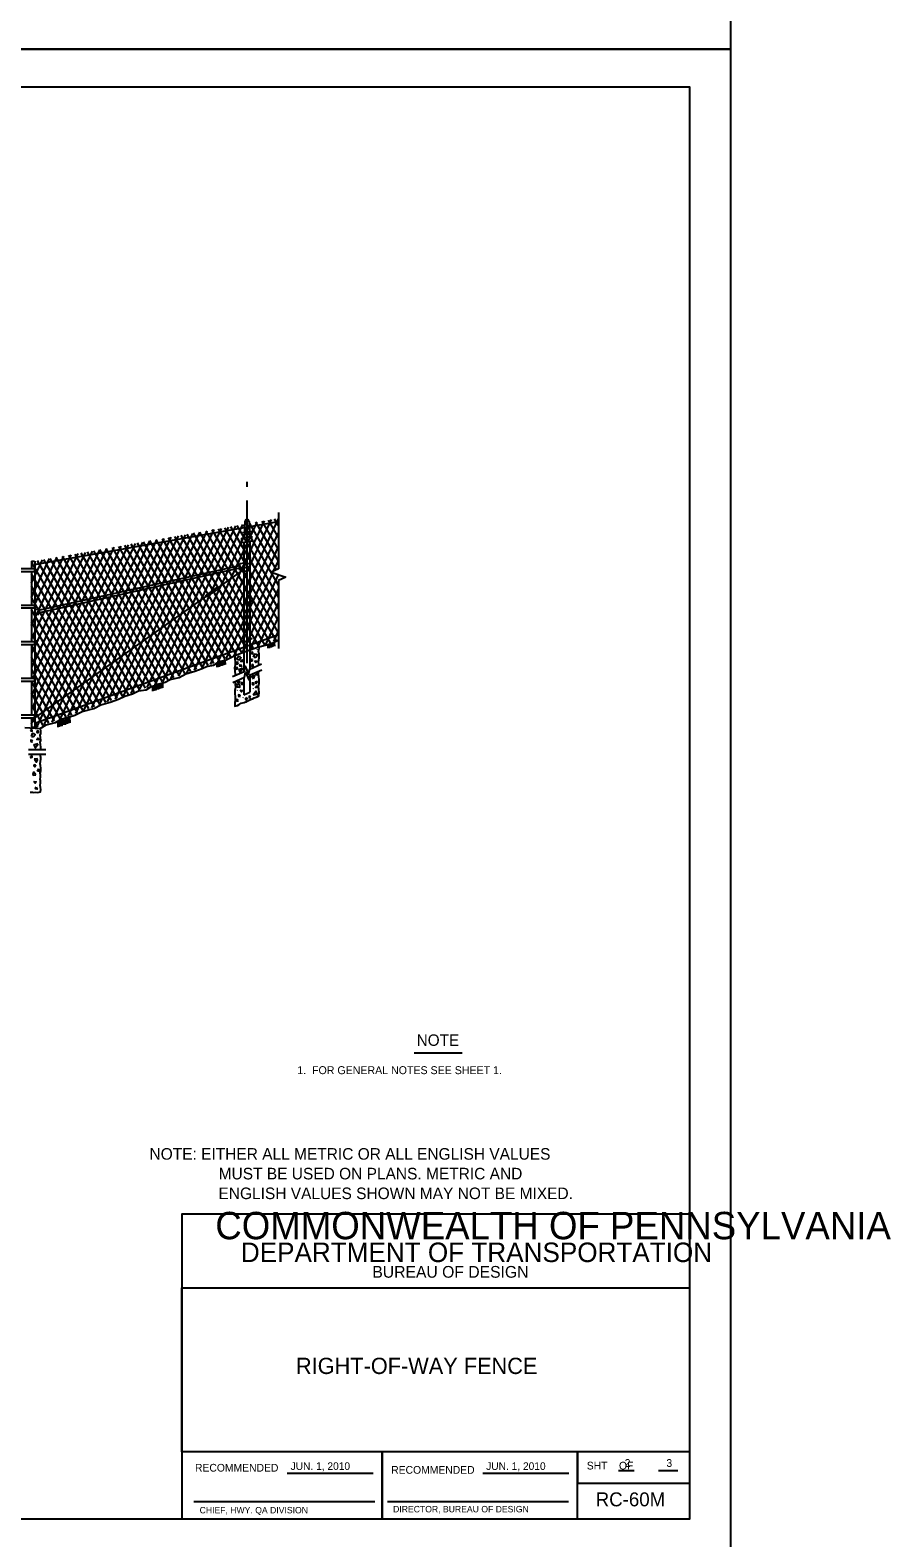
# Model space of a CAD drawing. Extents: x 13 to 918, y -903 to 879.
# Drawn here: x 579 to 917, y -302 to 292 of the extents above; entities that cross this region are included whole.
import ezdxf

# ---------------------------------------------------------------- set-up
doc = ezdxf.new("R2010")
doc.units = 0
for name, color, linetype in [('1', 7, 'Continuous'), ('2', 7, 'Continuous'), ('3', 7, 'Continuous'), ('40', 7, 'Continuous'), ('PLT-BNDY', 7, 'Continuous')]:
    doc.layers.add(name, color=color, linetype=linetype)

msp = doc.modelspace()

# ---------------------------------------------------------------- linework, layer by layer
at = {"layer": '1'}
for p, q in [((672.06425, 50.0655), (672.083, 48.8865)), ((672.3455, 50.16775), (672.362, 48.96775)), ((672.6245, 50.26775), (672.64325, 49.06775)), ((672.90375, 50.36975), (672.9225, 49.16975)), ((673.80175, 50.35725), (672.90575, 50.34275)), ((673.80575, 50.074), (672.91, 50.0615)), ((673.812, 49.79475), (672.912, 49.778)), ((673.81425, 49.5115), (672.91825, 49.49675)), ((673.05175, 49.21775), (672.9225, 49.2155)), ((673.7975, 50.6365), (673.63075, 50.63425)), ((673.78925, 50.69275), (673.80575, 49.49275)), ((674.06825, 50.79475), (674.087, 49.59475)), ((674.3455, 50.89675), (674.36625, 49.69475)), ((674.62875, 50.999), (674.6475, 49.79675)), ((651.95175, 42.9115), (651.9745, 41.4115)), ((652.31, 43.0405), (652.333, 41.5135)), ((652.66625, 43.16975), (652.68925, 41.64275)), ((653.0205, 43.299), (653.0455, 41.77175)), ((654.16425, 43.28225), (653.0225, 43.2635)), ((654.1705, 42.924), (653.02875, 42.90725)), ((654.17675, 42.5655), (653.033, 42.54675)), ((654.18075, 42.20725), (653.03925, 42.1885)), ((653.21, 41.83225), (653.0455, 41.83025)), ((654.158, 43.6385), (653.9455, 43.6365)), ((654.1475, 43.70925), (654.1705, 42.18225)), ((654.50375, 43.8385), (654.52675, 42.3115)), ((654.858, 43.96775), (654.883, 42.4405)), ((655.21625, 44.099), (655.23925, 42.56975)), ((626.6205, 33.7905), (626.6475, 31.96775)), ((627.05375, 33.94675), (627.083, 32.09275)), ((627.487, 34.103), (627.51425, 32.249)), ((627.91825, 34.2615), (627.9475, 32.40725)), ((629.30575, 34.2405), (627.9205, 34.21775)), ((629.31425, 33.80525), (627.92675, 33.78425)), ((629.3205, 33.36975), (627.933, 33.34675)), ((629.32675, 32.93425), (627.93925, 32.9115)), ((628.1475, 32.48025), (627.9475, 32.478)), ((629.2995, 34.674), (629.04125, 34.66975)), ((629.285, 34.75925), (629.31425, 32.90525)), ((629.71825, 34.9155), (629.7455, 33.0615)), ((630.1475, 35.074), (630.17875, 33.21775)), ((630.583, 35.23225), (630.612, 33.376)), ((589.383, 20.00725), (589.41625, 17.8635)), ((589.89325, 20.19275), (589.92675, 18.00925)), ((590.40175, 20.376), (590.435, 18.19475)), ((590.91, 20.5615), (590.94325, 18.38025)), ((592.54325, 20.5365), (590.912, 20.50925)), ((592.55175, 20.024), (590.9205, 20.001)), ((592.56, 19.5135), (590.92675, 19.4865)), ((592.56625, 19.001), (590.935, 18.974)), ((591.18075, 18.4655), (590.94325, 18.4635)), ((592.535, 21.04675), (592.23075, 21.04275)), ((592.51825, 21.14675), (592.55175, 18.9655)), ((593.02675, 21.33225), (593.06, 19.151)), ((593.533, 21.51775), (593.5705, 19.33425)), ((594.0455, 21.703), (594.07875, 19.51975)), ((679.7155, -276.08075), (713.602, -276.08075)), ((756.7135, -276.08075), (790.5835, -276.08075)), ((810.116, -275.09675), (816.258, -275.09675)), ((825.9255, -275.09675), (833.572, -275.09675)), ((643.0125, -287.26844), (714.262, -287.26844)), ((719.182, -287.26844), (790.522, -287.26844))]:
    msp.add_line(p, q, dxfattribs=at)
msp.add_lwpolyline([(838.2505, -294.06975), (838.2505, 269.93025), (52.2505, 269.93025), (52.2505, -294.06975), (838.2505, -294.06975), (838.2505, -267.71075), (638.2505, -267.71075), (638.2505, -203.03325), (838.2505, -203.03325), (838.2505, -174.06975), (638.2505, -174.06975), (638.2505, -294.06975), (717.052, -294.06975), (717.052, -267.71075), (717.052, -294.06975), (794.052, -294.06975), (794.052, -267.71075), (794.052, -280.02725), (838.2505, -280.02725)], dxfattribs=at)
at = {"layer": '2'}
for p, q in [((663.85375, 114.43025), (663.85375, 112.55925)), ((663.85375, 107.15925), (663.85375, 43.03225)), ((676.27675, 102.426), (676.27675, 80.1905)), ((580.2495, 81.89675), (676.27675, 98.828)), ((580.2495, 81.89675), (676.27675, 98.828)), ((662.11625, 94.474), (665.69325, 95.103)), ((663.0495, 98.79475), (662.73075, 92.49275)), ((663.85375, 96.6385), (663.85375, 96.6385)), ((664.72875, 98.79475), (664.96825, 92.8865)), ((661.8955, 92.34675), (665.7495, 93.024)), ((661.8955, 90.58025), (661.8955, 92.34675)), ((661.8955, 90.58025), (665.7495, 91.25925)), ((662.67875, 90.71775), (662.67875, 39.7865)), ((665.02875, 91.13225), (665.02875, 40.81775)), ((665.7495, 91.25925), (665.7495, 93.024)), ((579.09125, 83.18225), (580.26625, 83.18225)), ((579.09125, 83.18225), (579.09125, 80.401)), ((580.3205, 83.18225), (580.3205, 17.81775)), ((662.00375, 83.824), (665.58075, 84.453)), ((574.61425, 80.3865), (580.37675, 80.3865)), ((574.61425, 79.2115), (580.37675, 79.2115)), ((579.09125, 79.199), (579.09125, 65.97175)), ((580.37675, 79.2115), (580.37675, 80.3865)), ((581.81425, 63.9365), (661.05375, 81.53025)), ((581.85375, 62.86775), (661.05375, 80.6135)), ((653.05575, 73.09475), (662.6995, 79.94675)), ((661.05375, 79.65725), (661.05375, 82.28025)), ((661.05375, 79.65725), (662.6995, 79.94675)), ((661.108, 82.25725), (662.75375, 82.54675)), ((662.658, 81.9365), (665.17675, 82.38025)), ((662.658, 79.253), (662.658, 81.9365)), ((662.658, 79.253), (665.17675, 79.69675)), ((662.66825, 80.6385), (665.18075, 81.08025)), ((665.17675, 79.69675), (665.17675, 82.38025)), ((676.27675, 80.1905), (673.333, 78.8905)), ((673.333, 78.8905), (679.2205, 76.87175)), ((647.912, 69.8405), (652.31, 72.9655)), ((648.1955, 69.24475), (652.60575, 72.376)), ((652.31, 72.9655), (653.05575, 73.09475)), ((653.05575, 73.09475), (652.60575, 72.376)), ((679.2205, 76.87175), (676.27675, 75.57175)), ((676.27675, 75.57175), (676.27675, 48.87175)), ((574.61425, 65.949), (580.37675, 65.949)), ((578.86625, 20.39275), (647.533, 69.174)), ((580.37675, 64.774), (580.37675, 65.949)), ((647.533, 69.174), (647.912, 69.8405)), ((648.1955, 69.24475), (647.533, 69.174)), ((661.95175, 65.94275), (665.96625, 67.7155)), ((574.61425, 64.774), (580.37675, 64.774)), ((579.09125, 65.06775), (579.09125, 65.06775)), ((579.09125, 64.7885), (579.09125, 51.50525)), ((580.3205, 64.174), (581.885, 64.449)), ((580.3205, 62.0905), (581.885, 62.3655)), ((581.885, 64.449), (581.885, 62.3655)), ((580.3205, 19.38425), (676.27675, 54.30925)), ((580.3205, 19.38425), (676.27675, 54.30925)), ((574.61425, 51.5135), (580.37675, 51.5135)), ((574.61425, 50.3385), (580.37675, 50.3385)), ((579.09125, 50.63225), (579.09125, 50.63225)), ((579.09125, 50.32175), (579.09125, 37.001)), ((580.37675, 50.3385), (580.37675, 51.5135)), ((659.158, 47.71975), (659.158, 47.71975)), ((661.96425, 51.06975), (665.97875, 52.84275)), ((663.85375, 47.71975), (663.85375, 47.71975)), ((663.85375, 47.71975), (663.85375, 47.71975)), ((663.85375, 47.71975), (663.85375, 47.71975)), ((668.5475, 47.71975), (668.5475, 47.71975)), ((574.61425, 37.076), (580.37675, 37.076)), ((574.61425, 35.901), (580.37675, 35.901)), ((579.09125, 35.93225), (579.09125, 22.63025)), ((580.37675, 35.901), (580.37675, 37.076)), ((662.67875, 37.30525), (662.67875, 30.53225)), ((665.02875, 38.451), (665.02875, 31.56975)), ((662.67875, 30.53225), (665.02875, 31.56975)), ((663.85375, 27.38225), (663.85375, 27.38225)), ((574.61425, 22.6405), (580.37675, 22.6405)), ((574.61425, 21.4655), (580.37675, 21.4655)), ((579.09125, 21.44675), (579.09125, 17.81775)), ((580.37675, 21.4655), (580.37675, 22.6405)), ((579.09125, 17.81775), (580.26625, 17.81775)), ((582.4205, 17.29675), (582.4205, 17.29675)), ((577.91625, 8.9655), (584.683, 8.9655)), ((577.91625, 7.20925), (584.683, 7.20925))]:
    msp.add_line(p, q, dxfattribs=at)
for points in [[(618.32875, 31.151), (648.1705, 95.14475)], [(621.44325, 32.28425), (650.987, 95.6405)], [(624.558, 33.41775), (653.80575, 96.1385)], [(627.6725, 34.551), (656.6225, 96.63425)], [(630.787, 35.68425), (659.44125, 97.13225)], [(633.90175, 36.81775), (662.258, 97.628)], [(637.01625, 37.953), (665.07675, 98.126)], [(640.13075, 39.0865), (667.89325, 98.62175)], [(643.2455, 40.21975), (670.712, 99.11975)], [(646.362, 41.353), (673.52875, 99.6155)], [(673.137, 51.099), (647.7475, 95.06975)], [(649.47675, 42.4865), (676.27675, 99.9615)], [(675.3725, 51.9135), (650.20375, 95.503)], [(676.27675, 55.0385), (652.662, 95.9365)], [(676.27675, 59.724), (655.11825, 96.36975)], [(676.27675, 64.4135), (657.5745, 96.803)], [(676.27675, 69.099), (660.03075, 97.2365)], [(676.27675, 73.7885), (662.487, 97.66975)], [(675.485, 79.84275), (664.94125, 98.101)], [(676.27675, 83.1635), (667.3995, 98.53425)], [(676.2745, 87.851), (669.85375, 98.96775)], [(676.27675, 92.5365), (672.312, 99.401)], [(676.27675, 97.224), (674.76825, 99.83425)], [(580.95375, 17.54675), (614.358, 89.18225)], [(584.06825, 18.68025), (617.1725, 89.68025)], [(587.183, 19.8135), (619.99325, 90.176)], [(590.2975, 20.94675), (622.81, 90.674)], [(593.412, 22.08225), (625.62875, 91.16975)], [(596.52675, 23.2155), (628.44325, 91.6655)], [(599.64125, 24.349), (631.26425, 92.1635)], [(602.75575, 25.48225), (634.08075, 92.65925)], [(605.8705, 26.6155), (636.8995, 93.15725)], [(608.985, 27.749), (639.71625, 93.653)], [(612.0995, 28.88225), (642.535, 94.151)], [(615.21425, 30.01775), (645.35175, 94.64675)], [(644.06425, 40.51775), (615.81825, 89.4405)], [(646.30175, 41.33025), (618.2745, 89.874)], [(648.537, 42.14475), (620.73075, 90.30725)], [(650.7725, 42.9615), (623.185, 90.7385)], [(653.01, 43.774), (625.64325, 91.17175)], [(655.2455, 44.5885), (628.0975, 91.60525)], [(657.483, 45.401), (630.55375, 92.0385)], [(659.71825, 46.2155), (633.01, 92.47175)], [(661.95575, 47.03025), (635.46825, 92.90525)], [(664.19125, 47.84275), (637.9225, 93.3385)], [(666.42875, 48.65725), (640.38075, 93.77175)], [(668.66425, 49.47175), (642.835, 94.203)], [(670.90175, 50.28425), (645.29325, 94.6365)], [(652.59125, 43.61975), (676.27675, 94.4155)], [(579.05575, 68.93225), (586.18075, 84.2155)], [(579.07675, 52.34675), (594.633, 85.70525)], [(579.083, 57.899), (591.81425, 85.20725)], [(579.087, 74.549), (583.362, 83.71775)], [(579.09325, 19.103), (611.53925, 88.6865)], [(579.10575, 46.85725), (597.45175, 86.201)], [(579.1245, 41.353), (600.26825, 86.699)], [(579.13925, 24.753), (608.7225, 88.1885)], [(579.13925, 30.29275), (605.90175, 87.69275)], [(579.7225, 37.09275), (603.087, 87.19475)], [(580.22675, 65.901), (588.9975, 84.7115)], [(580.5225, 83.174), (580.54325, 83.21975)], [(612.75375, 29.12175), (581.42875, 83.376)], [(614.99125, 29.93425), (583.887, 83.80925)], [(617.22875, 30.749), (586.34125, 84.24275)], [(619.46425, 31.5635), (588.7975, 84.676)], [(621.70175, 32.378), (591.25375, 85.10925)], [(623.937, 33.19275), (593.71, 85.54275)], [(626.1725, 34.00725), (596.16625, 85.976)], [(628.41, 34.81975), (598.6245, 86.40925)], [(630.6455, 35.63425), (601.07875, 86.8405)], [(632.88075, 36.449), (603.535, 87.274)], [(635.11825, 37.2615), (605.99325, 87.70725)], [(637.35575, 38.076), (608.4475, 88.1405)], [(639.59125, 38.8885), (610.90375, 88.574)], [(641.82875, 39.703), (613.36, 89.00725)], [(655.70575, 44.75525), (676.27675, 88.86975)], [(674.487, 79.48425), (676.27675, 83.324)], [(608.28075, 27.49475), (579.08075, 78.074)], [(610.51825, 28.30725), (579.10175, 82.724)], [(658.8205, 45.8885), (674.02875, 78.503)], [(661.933, 47.01975), (676.27675, 77.78025)], [(606.0455, 26.68025), (579.083, 73.378)], [(665.0475, 48.153), (676.27675, 72.23225)], [(603.81, 25.8655), (579.11425, 68.6405)], [(668.162, 49.2865), (676.27675, 66.6885)], [(601.5725, 25.053), (579.07675, 64.0155)], [(671.27675, 50.41975), (676.27675, 61.1405)], [(599.337, 24.2385), (579.06, 59.35525)], [(597.10175, 23.424), (579.1455, 54.524)], [(674.39125, 51.55525), (676.27675, 55.59675)], [(576.39325, 17.724), (582.4205, 17.29675), (584.82875, 18.79275), (588.437, 19.63225), (591.012, 21.0655), (593.608, 21.73225), (596.108, 22.553), (599.0475, 23.98425), (603.55175, 25.149), (606.2995, 26.58025), (609.983, 27.66775), (613.3225, 28.83225), (615.7475, 29.99675), (618.83925, 30.9135), (621.187, 32.09675), (624.183, 32.59275), (626.035, 33.75725), (629.20175, 34.91975), (631.70175, 35.5885), (633.63075, 36.601), (637.14125, 37.34475), (639.737, 38.776), (643.40175, 39.9405), (646.2455, 40.951), (647.90575, 41.77175), (650.6725, 42.19275), (653.00175, 43.699), (655.6745, 44.36775), (659.158, 46.00925), (663.95575, 47.88025), (668.5475, 49.428), (672.14325, 50.38025), (674.4725, 51.14275), (676.27675, 52.2405)], [(594.86425, 22.6115), (579.11, 49.901)], [(668.512, 42.35925), (668.4225, 43.64275), (668.61425, 45.16975), (668.6705, 46.58225), (668.44125, 47.726), (668.65175, 48.776), (668.5475, 49.428)], [(592.62675, 21.79675), (579.087, 45.249)], [(658.15175, 37.724), (662.76825, 39.74275), (663.1225, 41.8155), (664.50175, 38.69275), (664.95175, 40.70525), (669.5495, 42.7135)], [(659.158, 46.00925), (659.05175, 44.73025), (659.28075, 43.624), (659.28075, 42.26775), (659.01425, 41.18025), (659.08925, 39.901), (659.185, 38.75725), (659.185, 38.203)], [(659.77875, 41.52175), (659.5495, 41.178), (659.74125, 40.701), (659.98925, 40.83425), (660.1975, 41.103), (659.81625, 41.61775)], [(660.40575, 43.349), (659.99325, 43.376), (659.67875, 42.96975), (659.91825, 42.82175), (660.25375, 42.778), (660.508, 43.3615)], [(661.337, 45.553), (660.508, 45.60725), (659.883, 44.79475), (660.362, 44.499), (661.0245, 44.40725), (661.537, 45.58225)], [(661.36, 42.5655), (661.7225, 41.7385), (661.05375, 41.8385), (661.29325, 42.603)], [(662.3975, 43.65725), (661.50175, 43.75725), (661.9225, 44.2865), (662.46425, 43.69675)], [(666.083, 44.478), (665.6705, 44.50525), (665.35575, 44.099), (665.5955, 43.951), (665.93075, 43.90725), (666.185, 44.4905)], [(665.52675, 47.22175), (665.708, 46.851), (666.21825, 46.778), (666.22675, 47.05925), (666.0975, 47.374), (665.462, 47.301)], [(666.07675, 41.73025), (666.308, 42.074), (666.11425, 42.549), (665.86625, 42.4155), (665.658, 42.149), (666.037, 41.63425)], [(666.562, 45.4155), (667.387, 45.3615), (668.01625, 46.16975), (667.537, 46.4655), (666.86625, 46.55725), (666.35375, 45.3865)], [(666.9205, 43.9655), (667.81825, 43.8655), (667.3975, 43.3365), (666.85375, 43.926)], [(588.15375, 20.16775), (579.085, 35.874)], [(590.39125, 20.98225), (579.10175, 40.5385)], [(658.2745, 35.45925), (662.89325, 37.478), (663.2475, 39.551), (664.62675, 36.428), (665.0745, 38.4405), (669.6745, 40.449)], [(659.185, 35.85525), (659.28075, 34.7115), (659.37675, 33.46975), (659.05175, 32.4385), (659.05175, 31.1615), (659.2245, 29.653), (659.2245, 28.5655), (659.11, 27.38225), (659.158, 26.103), (660.1975, 26.36975), (660.82675, 26.7905), (661.6475, 27.23025), (662.7725, 27.478), (663.65175, 27.878), (664.41425, 28.3365), (665.29325, 28.699), (666.01825, 28.9655), (666.74325, 29.36775), (667.8495, 29.7865), (668.5475, 30.20725), (668.65175, 31.524), (668.48075, 32.74475), (668.385, 33.9655), (668.65175, 35.149), (668.6705, 36.58025), (668.55575, 37.66975), (668.4225, 38.853), (668.5725, 39.98425)], [(660.9205, 36.04675), (660.508, 36.074), (660.19325, 35.66775), (660.433, 35.51975), (660.76825, 35.476), (661.0225, 36.05925)], [(662.30575, 40.90925), (661.235, 39.45525), (660.73925, 40.7135), (662.30175, 41.0635)], [(666.40575, 36.901), (666.91, 38.15925), (666.11, 38.09675), (665.76, 37.71775), (666.43075, 36.8635)], [(668.01425, 35.803), (667.47875, 35.078), (667.23075, 35.70725), (668.012, 35.88025)], [(668.137, 39.05725), (667.7245, 39.08425), (667.41, 38.678), (667.6495, 38.53025), (667.985, 38.4865), (668.23925, 39.06975)], [(585.91825, 19.353), (579.0725, 31.2115)], [(659.70175, 34.426), (660.06825, 33.68425), (661.085, 33.54275), (661.10175, 34.10525), (660.84325, 34.73425), (659.5725, 34.5885)], [(661.208, 30.08225), (661.0245, 30.453), (660.51625, 30.52175), (660.508, 30.2405), (660.635, 29.93025), (661.2705, 30.001)], [(661.212, 32.40925), (662.11, 32.30925), (661.68925, 31.78025), (661.1455, 32.36975)], [(662.2725, 34.876), (662.08925, 35.24675), (661.58075, 35.3155), (661.5725, 35.03425), (661.70175, 34.72175), (662.335, 34.79275)], [(665.3705, 29.5865), (665.187, 29.95725), (664.67875, 30.026), (664.6705, 29.74475), (664.7975, 29.43425), (665.433, 29.50525)], [(665.887, 35.0115), (666.0705, 34.6405), (666.57875, 34.56775), (666.587, 34.849), (666.458, 35.1655), (665.8225, 35.09275)], [(666.283, 30.5405), (667.35375, 31.9905), (667.8495, 30.73225), (666.283, 30.3865)], [(668.158, 33.35925), (667.262, 33.45925), (667.683, 33.9885), (668.2245, 33.399)], [(583.68075, 18.5405), (579.108, 26.4635)], [(660.462, 28.2655), (660.27875, 28.6385), (659.7705, 28.70725), (659.762, 28.426), (659.88925, 28.1135), (660.5245, 28.18425)], [(663.4705, 29.353), (663.24125, 29.00925), (663.433, 28.53225), (663.68075, 28.6655), (663.88925, 28.93425), (663.508, 29.449)], [(579.29125, 21.45925), (581.43925, 17.7635)], [(578.65375, 16.68225), (578.835, 16.3115), (579.3455, 16.2385), (579.35375, 16.51975), (579.2245, 16.83425), (578.58925, 16.7615)], [(579.50175, 12.251), (579.31825, 12.624), (578.81, 12.69275), (578.80175, 12.4115), (578.92875, 12.099), (579.56425, 12.16975)], [(579.05175, 14.15525), (579.87675, 14.101), (580.50575, 14.90925), (580.02675, 15.20525), (579.35575, 15.29675), (578.84325, 14.126)], [(581.5225, 15.578), (581.75375, 15.92175), (581.56, 16.39675), (581.312, 16.2635), (581.10375, 15.99675), (581.483, 15.48225)], [(582.04125, 12.8115), (581.1455, 12.9115), (581.56625, 13.4405), (582.108, 12.851)], [(582.67875, 9.02175), (582.67875, 9.9385), (582.60375, 11.04475), (582.4495, 11.84675), (582.71825, 12.57175), (582.64125, 13.79275), (582.508, 14.6135), (582.71825, 15.378), (582.75575, 16.21775), (582.60375, 17.29675)], [(578.48075, -7.774), (579.4725, -7.774), (579.98925, -7.90725), (580.6955, -7.83025), (581.47675, -7.86775), (582.10575, -7.83025), (582.60375, -7.70325), (582.71825, -6.78025), (582.5455, -5.9595), (582.508, -5.04475), (582.60375, -4.28025), (582.60375, -3.2885), (582.508, -2.71575), (582.64125, -1.85725), (582.64125, -0.97825), (582.508, -0.29275), (582.71825, 0.56775), (582.71825, 1.7115), (582.5455, 2.6865), (582.4705, 3.3155), (582.5455, 4.34675), (582.71825, 5.20525), (582.7745, 5.9115), (582.412, 7.01775), (582.4225, 7.20925)], [(579.1205, 5.724), (579.3495, 6.06775), (579.15575, 6.54275), (578.908, 6.40925), (578.70175, 6.14275), (579.08075, 5.628)], [(581.68925, 11.1865), (580.61825, 9.73225), (580.1225, 10.9905), (581.685, 11.3405)], [(580.76, -0.96575), (579.9225, 0.09675), (579.57675, -0.624), (579.73075, -1.11975), (580.80575, -0.96575)], [(580.66425, 2.9155), (580.25175, 2.94275), (579.937, 2.5365), (580.17675, 2.3885), (580.512, 2.34475), (580.76625, 2.928)], [(580.183, 5.149), (581.0205, 4.08225), (581.36625, 4.80725), (581.212, 5.303), (580.14125, 5.149)], [(581.30575, 0.976), (581.487, 0.60525), (581.9975, 0.53225), (582.00575, 0.8135), (581.87675, 1.128), (581.24125, 1.05525)], [(579.983, -3.576), (580.88075, -3.676), (580.46, -4.20525), (579.91625, -3.61575)], [(580.8975, -5.75525), (581.26, -6.58225), (580.59125, -6.48225), (580.83075, -5.71775)]]:
    msp.add_lwpolyline(points, dxfattribs=at)
msp.add_arc((663.88922, 98.79479), 0.83958, 0, 180, dxfattribs=at)
at = {"layer": '3'}
msp.add_line((729.683, -110.44075), (748.63275, -110.44075), dxfattribs=at)
at = {"layer": 'PLT-BNDY'}
for points in [[(13.2505, 878.93025), (854.2505, 878.93025), (854.2505, 284.93025), (13.2505, 284.93025)], [(13.2505, 284.93025), (854.2505, 284.93025), (854.2505, -309.06975), (13.2505, -309.06975)]]:
    msp.add_lwpolyline(points, close=True, dxfattribs=at)

# ---------------------------------------------------------------- texts
at = {"layer": '1'}
for s, height, p in [('COMMONWEALTH OF PENNSYLVANIA', 10.7833725, (651.4015, -183.92625)), ('DEPARTMENT OF TRANSPORTATION', 7.6842885, (661.4625, -192.9205)), ('BUREAU OF DESIGN', 4.6220925, (713.237, -199.08275)), ('RIGHT-OF-WAY FENCE', 6.4000005, (683.15375, -237.017)), ('RECOMMENDED', 3.048, (643.414, -275.47625)), ('JUN. 1, 2010', 3, (681.05403, -274.81375)), ('RECOMMENDED', 3.048, (720.658, -276.3125)), ('JUN. 1, 2010', 3, (758.05203, -274.81375)), ('SHT    OF', 3.048, (797.656, -274.63975)), ('APPROVED', 0.019212, (681.2735, -276.13825)), ('RC-60M', 5.500001, (801.16775, -289.153)), ('CHIEF, HWY. QA DIVISION', 2.5399995, (645.22964, -291.92516)), ('DIRECTOR, BUREAU OF DESIGN', 2.5399995, (721.41164, -291.52644))]:
    msp.add_text(s, height=height, dxfattribs=at).set_placement(p)
at = {"layer": '2'}
for p in [(667.808, 47.79675), (659.958, 31.728), (662.237, 28.86775), (666.258, 32.40925)]:
    msp.add_text('.', height=3.125, rotation=60, dxfattribs=at).set_placement(p)
for s, p in [('2', (812.598, -273.60725)), ('3', (829.00975, -273.60725))]:
    msp.add_text(s, height=3.048, dxfattribs=at).set_placement(p)
at = {"layer": '3'}
for s, height, p in [('NOTE', 4.5, (730.6975, -107.73075)), ('1.  FOR GENERAL NOTES SEE SHEET 1.', 3.1249995, (683.6815, -118.8815))]:
    msp.add_text(s, height=height, dxfattribs=at).set_placement(p)
at = {"layer": '40'}
for s, p in [('NOTE: EITHER ALL METRIC OR ALL ENGLISH VALUES', (625.4995, -152.581)), ('MUST BE USED ON PLANS. METRIC AND', (652.72425, -160.349)), ('ENGLISH VALUES SHOWN MAY NOT BE MIXED.', (652.65175, -168.11725))]:
    msp.add_text(s, height=4.558749, dxfattribs=at).set_placement(p)

doc.saveas('drawing.dxf')
